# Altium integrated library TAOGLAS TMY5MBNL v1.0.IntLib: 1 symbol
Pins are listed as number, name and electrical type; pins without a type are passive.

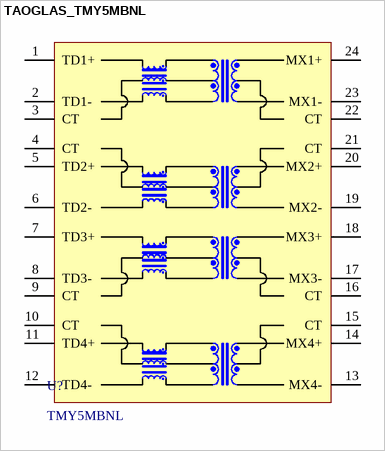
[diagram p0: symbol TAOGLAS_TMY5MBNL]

## TAOGLAS_TMY5MBNL
designator U?, comment TMY5MBNL
1G Base-T LAN Transformer Single Port and 24pin SMT with low-profile PCMCIA; ComponentLibStatus: Created; MFG: Taoglas; Temp_High: +85C; Temp_Low: -40C
footprint TAOGLAS_TMY5MBNL (1G Base-T LAN Transformer Single Port and 24pin SMT with low-profile PCMCIA)
pins: 1 TD1+, 2 TD1-, 3 CT, 4 CT, 5 TD2+, 6 TD2-, 7 TD3+, 8 TD3-, 9 CT, 10 CT, 11 TD4+, 12 TD4-, 13 MX4-, 14 MX4+, 15 CT, 16 CT, 17 MX3-, 18 MX3+, 19 MX2-, 20 MX2+, 21 CT, 22 CT, 23 MX1-, 24 MX1+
